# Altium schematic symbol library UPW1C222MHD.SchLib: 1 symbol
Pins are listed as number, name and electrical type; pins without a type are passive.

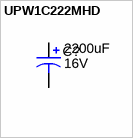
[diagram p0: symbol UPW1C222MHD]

## UPW1C222MHD
designator C?  value 2200uF  Value2Displayed: 16V  (hidden comment: UPW1C222MHD)
CAP, AL, 2200µF, 16V, +/- 20%, Radial; Manufacturer: Nichicon; Tolerance_%: 20; VDC_V: 16
footprint UPW1C222MHD (12.5Dx25T-5mmLS)
pins: 1 +, 2 -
